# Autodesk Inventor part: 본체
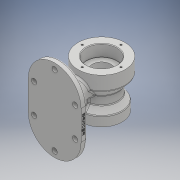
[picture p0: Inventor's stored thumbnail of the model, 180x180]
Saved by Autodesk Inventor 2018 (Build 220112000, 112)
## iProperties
Created: 2020-01
Part Number: 본체
Material: Generic
Document SubType Name: Modeling
Designer: Administrator
Density: 1 g/cm^3
Appearance: Default
Author: Administrator
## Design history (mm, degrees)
sketch "스케치1"
  geometry: L1 (45, 25)-(45, -25); L2 (-45, 25)-(-45, -25); A1 r 45 centre (0, 25) between (45, 25) and (-45, 25); A2 r 45 centre (0, -25) between (-45, -25) and (45, -25); 1 further point
  constraints: 4 end point, 4 point on circle, 2 centre point, 2 tangent, 2 vertical
  dimensions: "d2" = 45 radius of A1; "d3" = 45 radius of A2
extrude "돌출1" new body sketch "스케치1" distance "d4" = 10; taper "d5" = 0 deg
sketch "스케치2"
  geometry: L1 (45, -25)-(45, 25) reference; L2 (-45, 25)-(-45, -25) reference; L3 (-5, 3.199)-(-5, 30); L4 (5, 3.199)-(5, 30); L5 (0, 30)-(-5, 30); L6 (0, 30)-(5, 30); A1 r 45 centre (0, -25) between (-45, -25) and (45, -25) reference; A2 r 45 centre (0, 25) between (45, 25) and (-45, 25) reference; A3 r 45 centre (0, -25) between (-45, -25) and (45, -25) reference; A4 r 16 centre (0, -12) between (-5, 3.199) and (5, 3.199); 1 further point
  constraints: 8 end point, 2 perpendicular, 2 point on circle, 1 centre point
  dimensions: "d7" = 16 radius of A4
extrude "돌출2" join sketch "스케치2" distance "d13" = 80; taper "d14" = 0 deg
sketch "스케치3"
  geometry: L1 (0, 25)-(0, 70) reference; L2 (0, 70)-(10, 70) reference; L3 (80, 40)-(120, 40); L4 (120, 40)-(120, 16); L5 (80, 40)-(80, -40); L6 (80, -40)-(115, -40); L7 (115, -40)-(115, -24); L8 (120, 16)-(107.5, 1.103); L9 (115, -24)-(107.5, -13.289); L10 (107.5, 1.103)-(107.5, -13.289); L11 (80, 68.012)-(80, -106.966); 1 further point
  constraints: 18 end point, 3 perpendicular, 1 point on line, 1 vertical
  dimensions: "d18" = 40 distance of L3.start L3.end; "d19" = 24 distance of L3.end L4.end; "d20" = 80 distance of L3.start L5.end; "d21" = 35 distance of L5.end L6.end; "d22" = 16 distance of L6.end L7.end; "d23" = 40 deg angle of L4 L8; "d24" = 35 deg angle of L7 L9
revolve "회전1" sketch "스케치3" stored, may be unused: angle "d26" = 90 deg
sketch "스케치4"
  geometry: C1 r 26 at (0, 0); 1 further point
  constraints: 1 centre point
  dimensions: "d27" = 26 radius of C1
extrude "돌출3" cut sketch "스케치4" distance "d28" = 20; taper "d29" = 0 deg
sketch "스케치5"
  geometry: C1 r 16 at (0, 0); 1 further point
  constraints: 1 centre point
  dimensions: "d30" = 16 radius of C1
extrude "돌출4" cut sketch "스케치5" distance "d31" = 100; taper "d32" = 0 deg
sketch "스케치6"
  geometry: C1 r 20 at (0, 0); 1 further point
  constraints: 1 centre point
  dimensions: "d33" = 20 radius of C1
extrude "돌출5" cut sketch "스케치6" distance "d34" = 17; taper "d35" = 0 deg
chamfer "모따기1" distance "d36" = 1; stored, may be unused: second distance "d37" = 2, angle "d38" = 45 deg
fillet "모깎기1" dims "d39" = 3
fillet "모깎기2" dims "d40" = 3
fillet "모깎기3" dims "d41" = 3
fillet "모깎기4" dims "d42" = 3
sketch "스케치7"
  geometry: L1 (-45, 25)-(-45, -25) reference; L2 (45, -25)-(45, 25) reference; L3 (-35, -25)-(-35, 25); L4 (35, -25)-(35, 25); C1 r 4.5 at (-35, -25); C2 r 4.5 at (-35, 25); C3 r 4.5 at (35, 25); C4 r 4.5 at (35, -25); C5 r 4.5 at (0, -60); C6 r 4.5 at (0, 60); A1 r 45 centre (0, -25) between (-45, -25) and (45, -25) reference; A2 r 45 centre (0, 25) between (45, 25) and (-45, 25) reference; A3 r 45 centre (0, 25) between (45, 25) and (-45, 25) reference; A4 r 35 centre (0, 25) between (35, 25) and (-35, 25); A5 r 35 centre (0, -25) between (-35, -25) and (35, -25)
  constraints: 8 centre point, 6 coincident, 6 point on circle, 4 end point, 2 tangent, 2 vertical
  dimensions: "d45" = 4.5 radius of C1; "d46" = 4.5 radius of C2; "d47" = 4.5 radius of C3; "d48" = 4.5 radius of C4; "d49" = 4.5 radius of C5; "d50" = 4.5 radius of C6
extrude "돌출6" cut sketch "스케치7" distance "d51" = 17; taper "d52" = 0 deg
fillet "모깎기5" dims "d53" = 0.3
sketch "스케치8"
  geometry: A1 r 33 centre (0, 0) between (0, 33) and (-33, 0); 3 further points
  constraints: 4 point on circle, 1 centre point
  dimensions: "d54" = 33 radius of A1
hole "구멍1" sketch "스케치8" at (0, 33), (-33, 0), (33, 0), (0, -33) diameter "d55" = 3.242; stored, may be unused: countersink angle "d59" = 90 deg, drill point angle "d61" = 118 deg; dims "d56" = 9, "d57" = 4, "d58" = 2, "d60" = 11
sketch "스케치9"
  geometry: A1 r 27.5 centre (0, 0) between (-13.29, -24.075) and (13.29, -24.075); A2 r 27.5 centre (0, 0) between (13.29, -24.075) and (-13.29, -24.075) reference; 5 further points
  constraints: 4 point on circle, 1 centre point
  dimensions: "d62" = 27.5 radius of A1
hole "구멍2" sketch "스케치9" at (0, 27.5), (-27.5, 0), (27.5, 0), (0, -27.5) diameter "d63" = 3.242; stored, may be unused: countersink angle "d67" = 90 deg, drill point angle "d69" = 118 deg; dims "d64" = 9, "d65" = 4, "d66" = 2, "d68" = 11
sketch "스케치10"
  geometry: L1 (0, 0)-(-45, 0) reference; 2 further points
  constraints: 1 other
  dimensions: "d70" = 4 distance from line of L1 point (25, 4); "d71" = 70 horizontal distance of L1.end point (25, 4)
feature "엠보싱1" sketch "스케치10" dims "d72" = 0.5, "d73" = 0
node "솔리드1"
node "투영된 루프1"
node "투영된 루프2"
